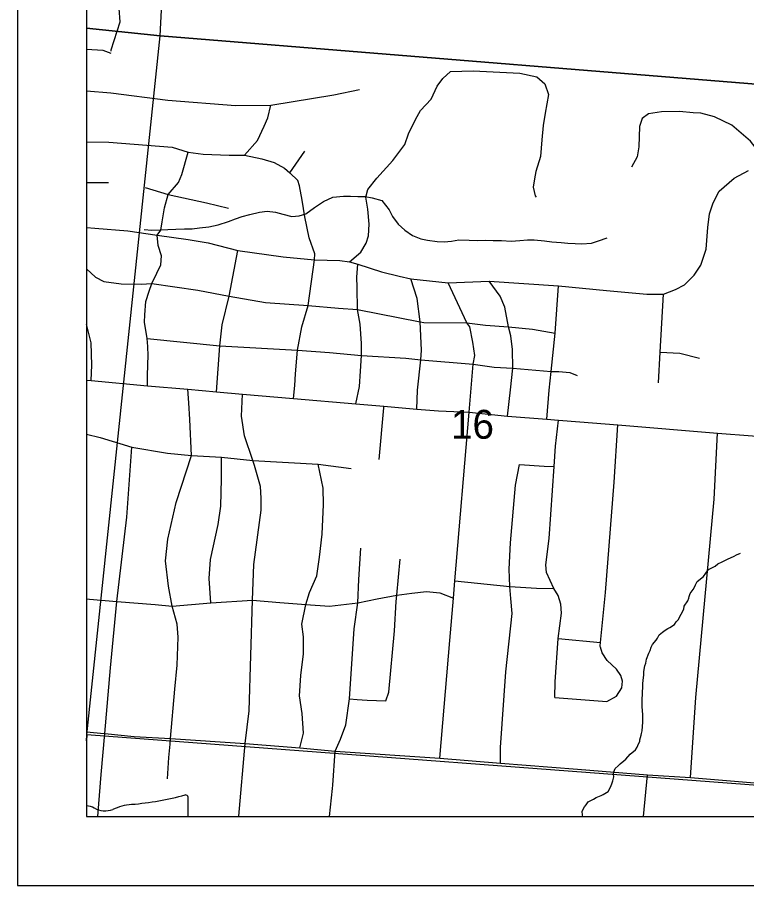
# Model space of a CAD drawing. Extents: x -7.3 to 34, y 0 to 22.
# Drawn here: x 2 to 3.055, y 14 to 15.258 of the extents above; entities that cross this region are included whole.
import ezdxf

# ---------------------------------------------------------------- set-up
doc = ezdxf.new("R2010")
doc.units = 0
for name, color, linetype in [('Default', 7, 'Continuous'), ('GM_X_City_Street', 7, 'Continuous'), ('GM_X_Corporation', 7, 'Continuous'), ('GM_X_County_Road', 7, 'Continuous'), ('GM_X_Minor_River', 7, 'Continuous'), ('GM_X_Section_Text', 7, 'Continuous'), ('SH_Data', 7, 'Continuous')]:
    doc.layers.add(name, color=color, linetype=linetype)

msp = doc.modelspace()

# ---------------------------------------------------------------- linework, layer by layer
at = {"layer": 'Default'}
msp.add_lwpolyline([(2.1, 14.1156), (2.1, 14.1), (2.2471, 14.1), (2.2471, 14.1282)], dxfattribs=at)
for centre, major_axis, start_param, end_param in [((2.1297, 14.3959), (0.3495, 0), 4.814394, 5.042369), ((2.2434, 14.1284), (0.00367, 0), 6.197627, 7.989034), ((2.0984, 14.0979), (0.0222, 0), 0.950623, 1.497668), ((2.127, 14.1297), (0.0267, 0), 4.08156, 5.145723), ((2.1742, 14.0619), (0.0703, 0), 1.699012, 2.107814)]:
    msp.add_ellipse(centre, major_axis=major_axis, ratio=0.8, start_param=start_param, end_param=end_param, dxfattribs=at)
at = {"layer": 'GM_X_City_Street'}
for p, q in [((2.1, 15.1512), (2.1355, 15.1484)), ((2.1, 15.0774), (2.1322, 15.0767)), ((2.3945, 15.0323), (2.4159, 15.0637)), ((2.1, 15.0183), (2.1319, 15.0182)), ((2.1848, 15.0111), (2.2184, 15.0012)), ((2.1, 14.953), (2.1121, 14.9522)), ((2.7829, 14.358), (2.8439, 14.3523)), ((2.7779, 14.2726), (2.8531, 14.2669)), ((2.4565, 14.1455), (2.4601, 14.1949)), ((2.9061, 14.1), (2.9122, 14.1604))]:
    msp.add_line(p, q, dxfattribs=at)
for points in [[(2.1356, 15.2086), (2.1359, 15.2107), (2.1489, 15.2511), (2.1474, 15.2701), (2.1236, 15.3097), (2.1129, 15.3237), (2.1, 15.3439)], [(2.1, 15.2113), (2.1239, 15.2098), (2.1352, 15.2055)], [(2.4806, 14.9036), (2.497, 14.9175), (2.505, 14.9306), (2.5083, 14.9411), (2.5091, 14.9578), (2.507, 14.9795), (2.5044, 14.9971), (2.5073, 15.008), (2.5203, 15.0244), (2.5434, 15.0501), (2.5607, 15.0736), (2.5661, 15.089), (2.5761, 15.1097), (2.5836, 15.1228), (2.5989, 15.1388), (2.6077, 15.1579), (2.6156, 15.1691), (2.6269, 15.1791), (2.6596, 15.1802), (2.7271, 15.1767), (2.7517, 15.1716), (2.7632, 15.161), (2.7689, 15.1457), (2.7637, 15.1189), (2.7609, 15.1011), (2.7589, 15.0802), (2.7571, 15.0559), (2.7505, 15.0341), (2.7483, 15.0235), (2.7465, 15.0114), (2.7492, 14.9988), (2.751, 14.9972)], [(2.1355, 15.1484), (2.2177, 15.1377), (2.3155, 15.13), (2.3668, 15.1303), (2.458, 15.1452), (2.4951, 15.1531)], [(2.3285, 15.058), (2.3473, 15.0791), (2.3573, 15.1001), (2.3626, 15.1118), (2.3668, 15.1303)], [(2.9781, 15.1194), (2.9581, 15.121), (2.9323, 15.1205), (2.9132, 15.1178), (2.9044, 15.111), (2.9004, 15.0993), (2.8994, 15.07), (2.897, 15.0557), (2.889, 15.0406)], [(3.0909, 14.9909), (3.0922, 15.0034), (3.0925, 15.0204), (3.0883, 15.0352), (3.0831, 15.0495), (3.061, 15.0783), (3.0341, 15.1016), (3.0088, 15.1136), (2.989, 15.1186), (2.9781, 15.1194)], [(2.1322, 15.0767), (2.2241, 15.0696), (2.2473, 15.0624), (2.2691, 15.0593), (2.3067, 15.0577), (2.3285, 15.058), (2.3537, 15.0524), (2.3718, 15.0474), (2.3868, 15.039), (2.3945, 15.0323), (2.4057, 15.0214)], [(2.1908, 14.8609), (2.1946, 14.872), (2.2018, 14.8868), (2.2078, 14.8989), (2.2085, 14.9119), (2.2036, 14.9272), (2.2023, 14.9423), (2.2076, 14.9495), (2.2095, 14.9612), (2.2129, 14.9816), (2.2184, 15.0012), (2.2333, 15.0183), (2.2378, 15.0299), (2.2473, 15.0624)], [(2.4302, 14.9061), (2.4669, 14.9054), (2.4806, 14.9036), (2.4927, 14.9001), (2.5272, 14.8892), (2.5525, 14.8827), (2.5693, 14.879), (2.6236, 14.8729), (2.6826, 14.8753), (2.7833, 14.8688), (2.8525, 14.862), (2.911, 14.8564), (2.9353, 14.8564), (2.9526, 14.8634), (2.9653, 14.8703), (2.9796, 14.884), (2.9894, 14.8987), (2.9969, 14.9218), (2.9991, 14.9532), (3.0015, 14.9731), (3.0072, 14.9888), (3.0158, 15.0057), (3.0376, 15.0244), (3.0582, 15.0355)], [(2.3996, 14.7057), (2.4015, 14.7243), (2.4023, 14.741), (2.4054, 14.7754), (2.4117, 14.8091), (2.4207, 14.8402), (2.4302, 14.9061), (2.4305, 14.915), (2.4223, 14.9382), (2.416, 14.9684), (2.4121, 14.9929), (2.4081, 15.0134), (2.4057, 15.0214)], [(2.2184, 15.0012), (2.2735, 14.989), (2.3056, 14.981)], [(2.1121, 14.9522), (2.16, 14.9481), (2.2023, 14.9423), (2.247, 14.9358), (2.2761, 14.9308), (2.3193, 14.9198), (2.3849, 14.9105), (2.4302, 14.9061)], [(2.2883, 14.7153), (2.2928, 14.782), (2.2965, 14.8121), (2.3066, 14.8538), (2.3193, 14.9198)], [(2.1, 14.8931), (2.1133, 14.8813), (2.125, 14.875), (2.1502, 14.8716), (2.1791, 14.8709), (2.1946, 14.872), (2.2614, 14.8623), (2.3066, 14.8538), (2.359, 14.8446), (2.4207, 14.8402), (2.465, 14.8362), (2.4922, 14.8344), (2.583, 14.8167), (2.5883, 14.8157), (2.6503, 14.8149), (2.6774, 14.8119), (2.7107, 14.8092), (2.7455, 14.8058), (2.7784, 14.7999)], [(2.4898, 14.6979), (2.4952, 14.7228), (2.4966, 14.745), (2.498, 14.7676), (2.4982, 14.7852), (2.4961, 14.8131), (2.4922, 14.8344), (2.4917, 14.8662), (2.4912, 14.8813), (2.4927, 14.9001)], [(2.5783, 14.6903), (2.579, 14.7178), (2.5841, 14.7616), (2.5851, 14.7755), (2.583, 14.8167), (2.5786, 14.8504), (2.5693, 14.879)], [(2.6116, 14.1848), (2.6258, 14.3552), (2.631, 14.4161), (2.6329, 14.4412), (2.6537, 14.6857), (2.6573, 14.7265), (2.6597, 14.7553), (2.6623, 14.7678), (2.6594, 14.7873), (2.6547, 14.8091), (2.6503, 14.8149), (2.6236, 14.8729)], [(2.7095, 14.68), (2.7136, 14.7183), (2.717, 14.7493), (2.7165, 14.7766), (2.7141, 14.7964), (2.7107, 14.8092), (2.7055, 14.8376), (2.6987, 14.8537), (2.6826, 14.8753)], [(2.7662, 14.6755), (2.7696, 14.7176), (2.7724, 14.7446), (2.7784, 14.7999), (2.7833, 14.8688)], [(2.1883, 14.7239), (2.1885, 14.7376), (2.1888, 14.755), (2.1895, 14.7673), (2.1888, 14.781), (2.1878, 14.7926), (2.1842, 14.8163), (2.1846, 14.8269), (2.1858, 14.8462), (2.1908, 14.8609)], [(2.9278, 14.7284), (2.9302, 14.7728), (2.9353, 14.8564)], [(2.1066, 14.7315), (2.1077, 14.7537), (2.1067, 14.786), (2.1, 14.8132)], [(2.1878, 14.7926), (2.2928, 14.782), (2.4054, 14.7754), (2.4518, 14.7722), (2.498, 14.7676), (2.5621, 14.764), (2.5841, 14.7616), (2.6597, 14.7553), (2.6902, 14.751), (2.717, 14.7493), (2.7724, 14.7446), (2.7837, 14.7448), (2.7995, 14.7431), (2.8101, 14.7386)], [(2.9302, 14.7728), (2.9589, 14.7714), (2.9873, 14.7637)], [(2.2175, 14.1545), (2.2192, 14.1857), (2.2209, 14.205), (2.2217, 14.2133), (2.2278, 14.2846), (2.2313, 14.3193), (2.2326, 14.3598), (2.2311, 14.3785), (2.224, 14.4046), (2.2188, 14.4335), (2.2143, 14.4703), (2.2178, 14.502), (2.23, 14.5551), (2.2521, 14.623), (2.2497, 14.6753), (2.248, 14.6993), (2.2469, 14.7188)], [(2.3202, 14.1), (2.3203, 14.1005), (2.3295, 14.2058), (2.3357, 14.2533), (2.3403, 14.4133), (2.3422, 14.4652), (2.353, 14.5438), (2.353, 14.5613), (2.352, 14.578), (2.3433, 14.6083), (2.3407, 14.6159), (2.3289, 14.6516), (2.3243, 14.6798), (2.3258, 14.712)], [(2.5237, 14.6174), (2.5302, 14.6922), (2.5306, 14.6944)], [(2.7779, 14.2726), (2.7782, 14.2954), (2.7829, 14.358), (2.7873, 14.3948), (2.7865, 14.4077), (2.7827, 14.4204), (2.7764, 14.4302), (2.7656, 14.4535), (2.7646, 14.4646), (2.7695, 14.5028), (2.7771, 14.607), (2.7789, 14.6364), (2.783, 14.6742)], [(2.8437, 14.3465), (2.8434, 14.3474), (2.8439, 14.3523), (2.8512, 14.4247), (2.8635, 14.5845), (2.8689, 14.6673)], [(2.1, 14.6537), (2.1199, 14.6492), (2.1657, 14.6348), (2.2175, 14.6262), (2.2521, 14.623), (2.2956, 14.6204), (2.3407, 14.6159), (2.4355, 14.6102), (2.4832, 14.6041)], [(2.974, 14.1564), (2.9821, 14.2724), (3.0084, 14.5599), (3.0135, 14.6554)], [(2.1166, 14.1), (2.1211, 14.1611), (2.1265, 14.2203), (2.135, 14.3153), (2.1441, 14.4114), (2.1584, 14.5335), (2.1657, 14.6348)], [(2.2802, 14.4094), (2.2776, 14.445), (2.2797, 14.4721), (2.2904, 14.5229), (2.2946, 14.5494), (2.2952, 14.5893), (2.2956, 14.6204)], [(2.4088, 14.1994), (2.4139, 14.2206), (2.4124, 14.2492), (2.4083, 14.2748), (2.4104, 14.3044), (2.4143, 14.3358), (2.4142, 14.3605), (2.4117, 14.3786), (2.4174, 14.4074), (2.4226, 14.4245), (2.4332, 14.4485), (2.4374, 14.4759), (2.441, 14.5092), (2.4429, 14.5518), (2.4424, 14.5757), (2.4355, 14.6102)], [(2.6991, 14.1772), (2.6993, 14.2), (2.707, 14.3098), (2.7162, 14.3939), (2.7142, 14.4159), (2.7129, 14.4333), (2.7116, 14.4581), (2.7136, 14.4964), (2.7208, 14.5801), (2.7265, 14.6097)], [(2.7265, 14.6097), (2.7624, 14.6074), (2.7771, 14.607)], [(2.4601, 14.1949), (2.4677, 14.2123), (2.4755, 14.233), (2.4805, 14.2704), (2.4875, 14.3721), (2.4926, 14.4097), (2.4942, 14.4432), (2.4973, 14.4889)], [(2.5334, 14.2678), (2.5375, 14.2802), (2.5456, 14.369), (2.5482, 14.4115), (2.5491, 14.4207), (2.5541, 14.4729)], [(2.6329, 14.4412), (2.7129, 14.4333), (2.7514, 14.4309), (2.7764, 14.4302)], [(2.1, 14.4155), (2.1044, 14.415), (2.1441, 14.4114), (2.1992, 14.4071), (2.224, 14.4046), (2.2802, 14.4094), (2.3403, 14.4133), (2.3798, 14.4102), (2.4174, 14.4074), (2.4519, 14.4048), (2.4926, 14.4097), (2.5209, 14.4152), (2.5491, 14.4207), (2.571, 14.4237), (2.5923, 14.4261), (2.6115, 14.4242), (2.631, 14.4161)], [(2.8531, 14.2669), (2.8673, 14.2746), (2.8748, 14.2864), (2.8759, 14.296), (2.8735, 14.3041), (2.8669, 14.3137), (2.8535, 14.3262), (2.8466, 14.3374), (2.844, 14.3456), (2.8437, 14.3465)], [(2.4805, 14.2704), (2.4919, 14.2696), (2.5064, 14.2688), (2.5334, 14.2678)], [(2.4515, 14.1), (2.4561, 14.1406), (2.4565, 14.1455)]]:
    msp.add_lwpolyline(points, dxfattribs=at)
at = {"layer": 'GM_X_Corporation'}
for points in [[(2.1, 20.0921), (2.1, 14.1), (4.1756, 14.1), (4.1921, 14.279), (4.2199, 14.5807), (4.233, 14.7229), (4.246, 14.8644), (4.2591, 15.0066), (4.2655, 15.0758), (4.2701, 15.1232), (4.3152, 15.5847)], [(2.1, 17.0429), (2.1, 14.1), (4.1756, 14.1), (4.1921, 14.279), (4.2199, 14.5807), (4.233, 14.7229), (4.246, 14.8644), (4.2591, 15.0066), (4.2655, 15.0758), (4.2701, 15.1232), (4.3152, 15.5847)], [(2.1, 16.5161), (2.1, 14.1), (5.1665, 14.1)]]:
    msp.add_lwpolyline(points, dxfattribs=at)
for points in [[(2.1, 16.2578), (2.1, 15.242), (2.2068, 15.2308), (2.2589, 16.243)], [(2.2589, 16.243), (3.3302, 16.1779), (3.2417, 15.1468), (2.2068, 15.2308)], [(2.1, 15.242), (2.1, 14.2187), (2.1007, 14.2186), (2.2068, 15.2308)], [(2.2068, 15.2308), (3.2417, 15.1468), (3.1613, 14.1383), (2.1007, 14.2186)], [(2.1, 14.2187), (2.1, 14.2097), (2.1007, 14.2186)], [(2.1, 14.2097), (2.1, 14.1), (3.1578, 14.1), (3.1613, 14.1383), (2.1007, 14.2186)]]:
    msp.add_lwpolyline(points, close=True, dxfattribs=at)
at = {"layer": 'GM_X_County_Road'}
msp.add_line((2.1, 14.2227), (2.1256, 14.2204), dxfattribs=at)
for points in [[(2.1, 14.7322), (2.1066, 14.7315), (2.1883, 14.7239), (2.2469, 14.7188), (2.2883, 14.7153), (2.3258, 14.712), (2.3996, 14.7057), (2.4898, 14.6979), (2.5186, 14.6954)], [(2.5186, 14.6954), (2.5306, 14.6944), (2.5783, 14.6903), (2.6097, 14.6875), (2.6537, 14.6857), (2.7095, 14.68), (2.7662, 14.6755), (2.783, 14.6742), (2.8142, 14.6718), (2.8689, 14.6673), (3.0135, 14.6554), (3.0641, 14.6512), (3.0671, 14.6509), (3.1216, 14.6462), (3.1527, 14.6435), (3.1726, 14.6377), (3.1967, 14.6312), (3.2148, 14.6232)], [(2.1256, 14.2204), (2.1265, 14.2203), (2.1688, 14.2159), (2.2217, 14.2133), (2.3295, 14.2058), (2.4088, 14.1994), (2.4601, 14.1949), (2.6116, 14.1848), (2.6991, 14.1772), (2.8105, 14.1689), (2.9122, 14.1604), (2.974, 14.1564), (3.0782, 14.1479), (3.101, 14.1453), (3.1522, 14.1406)]]:
    msp.add_lwpolyline(points, dxfattribs=at)
at = {"layer": 'GM_X_Minor_River'}
for points in [[(2.1837, 14.9501), (2.1947, 14.9491), (2.2068, 14.95), (2.2178, 14.9502), (2.2292, 14.9507), (2.2421, 14.9512), (2.2528, 14.9514), (2.2638, 14.9527), (2.2771, 14.9539), (2.2908, 14.957), (2.3054, 14.9617), (2.3157, 14.9656), (2.3253, 14.9689), (2.3363, 14.9721), (2.3504, 14.9752), (2.3615, 14.9769), (2.3736, 14.9755), (2.3841, 14.9726), (2.397, 14.9693), (2.4076, 14.9702), (2.4176, 14.973), (2.4299, 14.9823), (2.443, 14.9907), (2.4564, 14.9969), (2.472, 14.9985), (2.4822, 14.9987), (2.4929, 14.9981), (2.5035, 14.9979), (2.5133, 14.9961), (2.5276, 14.9924), (2.5383, 14.9789), (2.5427, 14.969), (2.5512, 14.9581), (2.5608, 14.9492), (2.5717, 14.9414), (2.5837, 14.9366), (2.5935, 14.9349), (2.6075, 14.9327), (2.6178, 14.9325), (2.6284, 14.9334), (2.6391, 14.9351), (2.6539, 14.9348), (2.666, 14.9341), (2.6778, 14.9347), (2.6888, 14.9344), (2.7005, 14.9342), (2.7149, 14.9335), (2.7271, 14.9344), (2.7385, 14.9353), (2.748, 14.9355), (2.7631, 14.9337), (2.7733, 14.9323), (2.787, 14.9313), (2.7968, 14.9303), (2.8071, 14.9301), (2.8169, 14.9295), (2.831, 14.9304), (2.8409, 14.934), (2.8535, 14.9383)], [(2.9652, 14.4049), (2.9702, 14.4124), (2.9718, 14.4162), (2.9722, 14.4189), (2.9737, 14.423), (2.9783, 14.429), (2.9802, 14.4324), (2.9814, 14.4355), (2.9837, 14.4404), (2.9932, 14.4479), (2.9962, 14.4524), (3.0004, 14.458), (3.0099, 14.4625), (3.0137, 14.4663), (3.0198, 14.4689), (3.024, 14.4707), (3.0278, 14.473), (3.0376, 14.4774), (3.041, 14.4789), (3.0467, 14.4815)], [(2.8185, 14.1), (2.8178, 14.1021), (2.8175, 14.1078), (2.8206, 14.1142), (2.8232, 14.1172), (2.8259, 14.1214), (2.8339, 14.1251), (2.8377, 14.1277), (2.8449, 14.1303), (2.8479, 14.1318), (2.8551, 14.1363), (2.859, 14.1438), (2.8609, 14.1491), (2.862, 14.1518), (2.8632, 14.1578), (2.8629, 14.1616), (2.8633, 14.165), (2.8652, 14.1696), (2.8694, 14.1737), (2.8724, 14.1763), (2.8778, 14.1808), (2.8808, 14.1831), (2.8869, 14.1906), (2.8945, 14.1966), (2.8972, 14.2007), (2.8991, 14.2053), (2.9007, 14.2087), (2.9007, 14.2113), (2.9026, 14.2177), (2.9034, 14.2204), (2.9042, 14.2242), (2.9054, 14.2367), (2.9054, 14.2405), (2.9051, 14.2435), (2.9051, 14.2477), (2.9041, 14.2591), (2.9041, 14.267), (2.9046, 14.2803), (2.9054, 14.2875), (2.9054, 14.2921), (2.9058, 14.2977), (2.9067, 14.3046), (2.9067, 14.3099), (2.9079, 14.3182), (2.9094, 14.322), (2.9106, 14.328), (2.9137, 14.3367), (2.9156, 14.3405), (2.9172, 14.3454), (2.9191, 14.3492), (2.9244, 14.3556), (2.9263, 14.3582), (2.929, 14.3631), (2.9336, 14.3669), (2.9374, 14.3699), (2.9416, 14.3725), (2.9442, 14.374), (2.9511, 14.3781), (2.9534, 14.3819), (2.9564, 14.3849), (2.9606, 14.3932), (2.9645, 14.4003), (2.9652, 14.4049)]]:
    msp.add_lwpolyline(points, dxfattribs=at)
at = {"layer": 'SH_Data'}
for p, q in [((2, 21), (2, 14)), ((2.1, 20.9), (2.1, 14.1)), ((2.1, 14.1), (8.9, 14.1)), ((2.1, 14.1), (2.1, 14.1)), ((2, 14), (9, 14))]:
    msp.add_line(p, q, dxfattribs=at)

# ---------------------------------------------------------------- texts
at = {"layer": 'GM_X_Section_Text'}
msp.add_text('16', height=0.04186, rotation=0, dxfattribs=at).set_placement((2.6275, 14.6472))

doc.saveas('drawing.dxf')
